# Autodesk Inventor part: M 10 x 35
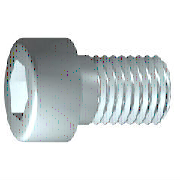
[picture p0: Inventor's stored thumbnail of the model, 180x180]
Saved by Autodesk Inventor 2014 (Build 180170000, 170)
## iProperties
IsCustomPart: 0
Created: 2009-02
Part Number: M 10 x 35
Material: 강, 연강
Description: 6각머리 태핑 나사
Document SubType Name: Modeling
Standard: KS B 1003
Designer: KYOUNG IL JANG
Standards Organization: KS
Language: ko-KR
Size Designation: M 10 x 35
Categories: <MemberInstance><Categories><Category DisplayName="조임쇠" InternalName="e4da775c-781d-43d5-af7c-5136215cf5a6" Mnemonic="FSTN"><Category DisplayName="볼트" InternalN
Density: 1 g/cm^3
Appearance: 강철
Author: KYOUNG IL JANG
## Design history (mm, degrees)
sketch "스케치1"
  geometry: L1 (-2.333, 0)-(35, 0); L2 (35, 0)-(35, 5); L3 (35, 5)-(3.75, 5); L4 (3.75, 5)-(2.83, 5); L5 (2.83, 5)-(0, 5); L6 (0, 5)-(0, 8); L7 (0, 8)-(-10, 8); L8 (-10, 8)-(-10, 4.619); L9 (-10, 4.619)-(-5, 4.619); L10 (-5, 4.619)-(-2.333, 0); L11 (-19, 0)-(44, 0) reference; L12 (0, -1.6)-(0, 9.6) reference; L13 (3.75, 5)-(0, 5)
  constraints: 22 end point, 6 parallel, 2 collinear, 2 perpendicular, 1 horizontal, 1 point on line
  dimensions: "d1" = 31.25 distance from line of L3.end L2 (= GEL); "d2" = 0.92028 distance of L4.end L3.end (computed from GAL); "d3" = 10 distance between parallel lines of L8 L6 (= KOH); "d4" = 5 distance of L8.end L9.end (= INTI); "d5" = 60 deg angle of L10 L1; "d6" = 10 diameter of L3 L1 (= GD); "d7" = 10 diameter of L5 L1 (= BDM); "d8" = 9.2376 diameter of L9 L1 (= 1.1547 x SW); "d9" = 16 diameter of L7 L1 (= KOD); "d26" = 35 distance between parallel lines of L12 L2 (= NLG)
revolve "본체" sketch "스케치1" stored, may be unused: angle "d10" = 90 deg
sketch "스케치2"
  geometry: L1 (0, -11.2)-(0, 11.2) reference; L2 (-11.2, 0)-(11.2, 0) reference; L3 (4.619, 0)-(2.309, -4); L4 (2.309, -4)-(-2.309, -4); L5 (-2.309, -4)-(-4.619, 0); L6 (-4.619, 0)-(-2.309, 4); L7 (-2.309, 4)-(2.309, 4); L8 (2.309, 4)-(4.619, 0); 2 further points
  constraints: 12 end point, 1 coincident, 1 horizontal alignment, 1 point on line, 12 other
extrude "슬롯" join sketch "스케치2" stored distance "d11" = 10; taper "d12" = 0 deg
workplane "Work Plane1"
fillet "Fillet2" dims "d30" = 0.1 (= R)
body "Solid1"
fillet "모깎기1" dims "d17" = 1 (= RR)
feature "스레드" dims "d13" = 31.25 (= GEL), "d14" = 0
chamfer "모따기1" distance "d15" = 0.92018 (= -0.5 x SPD + 0.5 x GD); stored, may be unused: second distance "d16" = 0.92018 (= GUL), angle "d27" = 45 deg
other parameters: "GD" = 10 (= NND) [user parameter; used in 2 equation terms], "NLG" = 35 [user parameter; used in 1 equation term], "GEL" = 31.25 [user parameter; used in 2 equation terms], "KOD" = 16 [user parameter; used in 1 equation term], "KOH" = 10 [user parameter; used in 1 equation term], "INTI" = 5 [user parameter; used in 1 equation term], "GAL" = 0.92018 (= 0.61345 x PTC) [user parameter; used in 1 equation term], "GUL" = 0.92018 (= 0.61345 x PTC) [user parameter; used in 1 equation term], "BDM" = 10 (= NND) [user parameter; used in 1 equation term], "SW" = 8 [user parameter; used in 2 equation terms], "RR" = 1 [user parameter; used in 1 equation term], "SPD" = 8.15965 (= NND - 1.2269 x PTC) [user parameter; used in 1 equation term], "d19" = 0, "d28" = 0, "d29" = 0, "R" = 0.1 [user parameter; used in 1 equation term], "PHH" = 0.4 [user parameter], "GD1" = 8.15965 (= THREADDIA - 1.2269 x PTC) [user parameter], "FAWI" = 45 deg [user parameter], "TPU" = 6.66667 (computed from PTC) [user parameter], "PTC" = 1.5 [user parameter; used in 5 equation terms], "TOA" = 30 deg [user parameter], "E0" = 9.24 (= 1.155 x SW) [user parameter]
